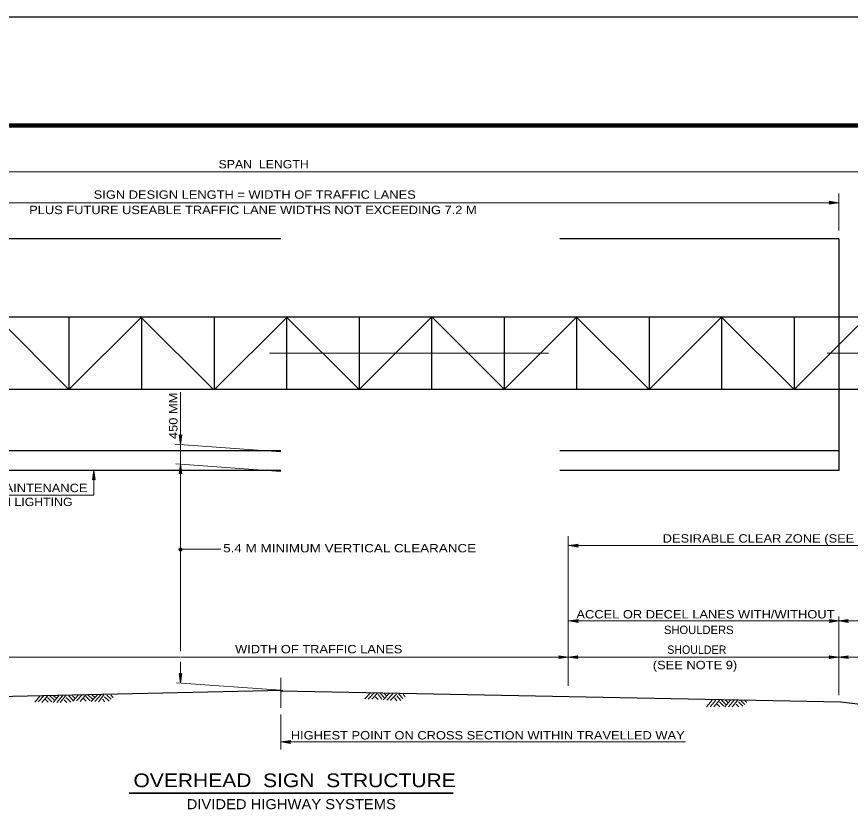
# Model space of a CAD drawing. Extents: x 312601.858 to 312602.699, y 144420.127 to 144420.721.
# Drawn here: x 312602.1123 to 312602.4113, y 144420.4365 to 144420.7208 of the extents above; entities that cross this region are included whole.
import ezdxf
from ezdxf.enums import TextEntityAlignment as Align

# ---------------------------------------------------------------- set-up
doc = ezdxf.new("R2010")
doc.units = 0
doc.header["$LTSCALE"] = 0.0012
doc.linetypes.add('DOT_DASHED', pattern=[7.7, 5, -1.2, 0.3, -1.2])
doc.linetypes.add('LONG_DASHED', pattern=[7.5, 6, -1.5])
for name, color, linetype, lineweight in [('1', 7, 'Continuous', 13), ('2', 7, 'Continuous', 13), ('39', 7, 'Continuous', 13)]:
    doc.layers.add(name, color=color, linetype=linetype, lineweight=lineweight)

msp = doc.modelspace()

# ---------------------------------------------------------------- hatches: boundary and pattern name
at = {"layer": '39'}
for points in [[(312602.404, 144420.6541), (312602.4037, 144420.6546), (312602.4071, 144420.6541), (312602.4037, 144420.6536)], [(312602.404, 144420.6541), (312602.4037, 144420.6546), (312602.4071, 144420.6541), (312602.4037, 144420.6536)], [(312602.1711, 144420.5705), (312602.1716, 144420.5708), (312602.1711, 144420.5674), (312602.1706, 144420.5708)], [(312602.1711, 144420.5705), (312602.1716, 144420.5708), (312602.1711, 144420.5674), (312602.1706, 144420.5708)], [(312602.14, 144420.555), (312602.1395, 144420.5547), (312602.14, 144420.5581), (312602.1405, 144420.5547)], [(312602.1711, 144420.5572), (312602.1706, 144420.5569), (312602.1711, 144420.5603), (312602.1716, 144420.5569)], [(312602.1711, 144420.5572), (312602.1706, 144420.5569), (312602.1711, 144420.5603), (312602.1716, 144420.5569)], [(312602.3134, 144420.5311), (312602.3137, 144420.5306), (312602.3103, 144420.5311), (312602.3137, 144420.5316)], [(312602.3134, 144420.5311), (312602.3137, 144420.5306), (312602.3103, 144420.5311), (312602.3137, 144420.5316)], [(312602.1717, 144420.5297, 1), (312602.1705, 144420.5297, 1)], [(312602.3134, 144420.5041), (312602.3137, 144420.5036), (312602.3103, 144420.5041), (312602.3137, 144420.5046)], [(312602.3134, 144420.5041), (312602.3137, 144420.5036), (312602.3103, 144420.5041), (312602.3137, 144420.5046)], [(312602.4041, 144420.5041), (312602.4038, 144420.5046), (312602.4072, 144420.5041), (312602.4038, 144420.5036)], [(312602.4041, 144420.5041), (312602.4038, 144420.5046), (312602.4072, 144420.5041), (312602.4038, 144420.5036)], [(312602.4102, 144420.5041), (312602.4105, 144420.5036), (312602.4071, 144420.5041), (312602.4105, 144420.5046)], [(312602.307, 144420.4911), (312602.3067, 144420.4916), (312602.3101, 144420.4911), (312602.3067, 144420.4906)], [(312602.3132, 144420.4911), (312602.3135, 144420.4906), (312602.3101, 144420.4911), (312602.3135, 144420.4916)], [(312602.3132, 144420.4911), (312602.3135, 144420.4906), (312602.3101, 144420.4911), (312602.3135, 144420.4916)], [(312602.404, 144420.4911), (312602.4037, 144420.4916), (312602.4071, 144420.4911), (312602.4037, 144420.4906)], [(312602.404, 144420.4911), (312602.4037, 144420.4916), (312602.4071, 144420.4911), (312602.4037, 144420.4906)], [(312602.4102, 144420.4911), (312602.4105, 144420.4906), (312602.4071, 144420.4911), (312602.4105, 144420.4916)], [(312602.4102, 144420.4911), (312602.4105, 144420.4906), (312602.4071, 144420.4911), (312602.4105, 144420.4916)], [(312602.1711, 144420.4849), (312602.1716, 144420.4852), (312602.1711, 144420.4818), (312602.1706, 144420.4852)], [(312602.1711, 144420.4849), (312602.1716, 144420.4852), (312602.1711, 144420.4818), (312602.1706, 144420.4852)], [(312602.2102, 144420.4607), (312602.2105, 144420.4602), (312602.2071, 144420.4607), (312602.2105, 144420.4612)]]:
    msp.add_hatch(color=256, dxfattribs=at).paths.add_polyline_path(points)

# ---------------------------------------------------------------- linework, layer by layer
at = {"layer": '1'}
for p, q in [((312602.1188, 144420.475), (312602.1208, 144420.4773)), ((312602.1201, 144420.4751), (312602.1222, 144420.4774)), ((312602.1214, 144420.4749), (312602.1234, 144420.4773)), ((312602.1242, 144420.4773), (312602.1258, 144420.4758)), ((312602.1254, 144420.4749), (312602.1275, 144420.4772)), ((312602.1256, 144420.4773), (312602.1265, 144420.4765)), ((312602.1267, 144420.4749), (312602.1288, 144420.4773)), ((312602.128, 144420.4748), (312602.1299, 144420.4773)), ((312602.131, 144420.4772), (312602.1325, 144420.4757)), ((312602.1324, 144420.4772), (312602.1332, 144420.4764)), ((312602.1325, 144420.4753), (312602.1345, 144420.4776)), ((312602.1338, 144420.4754), (312602.1359, 144420.4777)), ((312602.1351, 144420.4752), (312602.1371, 144420.4776)), ((312602.1379, 144420.4776), (312602.1395, 144420.4761)), ((312602.1391, 144420.4752), (312602.1412, 144420.4775)), ((312602.1393, 144420.4776), (312602.1402, 144420.4768)), ((312602.1404, 144420.4752), (312602.1425, 144420.4776)), ((312602.1417, 144420.4751), (312602.1436, 144420.4776)), ((312602.1447, 144420.4775), (312602.1462, 144420.476)), ((312602.1461, 144420.4775), (312602.1469, 144420.4767)), ((312602.2372, 144420.4762), (312602.2393, 144420.4784)), ((312602.2384, 144420.4761), (312602.2406, 144420.4784)), ((312602.2397, 144420.476), (312602.2418, 144420.4783)), ((312602.2419, 144420.4777), (312602.2433, 144420.476)), ((312602.2427, 144420.4782), (312602.2441, 144420.4767)), ((312602.2437, 144420.4758), (312602.2459, 144420.4781)), ((312602.2441, 144420.4782), (312602.2448, 144420.4773)), ((312602.2451, 144420.4757), (312602.2472, 144420.478)), ((312602.2463, 144420.4756), (312602.2485, 144420.4779)), ((312602.2486, 144420.4773), (312602.2501, 144420.4756)), ((312602.2494, 144420.4778), (312602.2508, 144420.4763)), ((312602.2509, 144420.4778), (312602.2516, 144420.4769)), ((312602.1226, 144420.476), (312602.1236, 144420.475)), ((312602.1234, 144420.4767), (312602.125, 144420.4751)), ((312602.1294, 144420.4758), (312602.1303, 144420.4748)), ((312602.1301, 144420.4766), (312602.1318, 144420.475)), ((312602.1363, 144420.4763), (312602.1373, 144420.4753)), ((312602.1371, 144420.477), (312602.1387, 144420.4754)), ((312602.1431, 144420.4761), (312602.144, 144420.4751)), ((312602.1438, 144420.4769), (312602.1455, 144420.4753)), ((312602.241, 144420.4769), (312602.242, 144420.4759)), ((312602.2478, 144420.4765), (312602.2487, 144420.4755)), ((312602.3597, 144420.4733), (312602.3617, 144420.4757)), ((312602.361, 144420.4733), (312602.363, 144420.4757)), ((312602.3623, 144420.4733), (312602.3643, 144420.4757)), ((312602.3635, 144420.4743), (312602.3645, 144420.4733)), ((312602.3643, 144420.4751), (312602.3659, 144420.4735)), ((312602.3651, 144420.4757), (312602.3666, 144420.4742)), ((312602.3663, 144420.4733), (312602.3683, 144420.4757)), ((312602.3665, 144420.4757), (312602.3673, 144420.4749)), ((312602.3676, 144420.4733), (312602.3696, 144420.4757)), ((312602.3689, 144420.4733), (312602.3709, 144420.4757)), ((312602.3703, 144420.4743), (312602.3713, 144420.4733)), ((312602.3711, 144420.4751), (312602.3727, 144420.4735)), ((312602.3719, 144420.4757), (312602.3734, 144420.4742)), ((312602.3733, 144420.4757), (312602.3741, 144420.4749))]:
    msp.add_line(p, q, dxfattribs=at)
at = {"layer": '2'}
for p, q in [((312602.14, 144420.5493), (312602.14, 144420.5581)), ((312602.064, 144420.5492), (312602.14, 144420.5492))]:
    msp.add_line(p, q, dxfattribs=at)
at = {"layer": '39', "lineweight": 25}
for p, q in [((312601.8578, 144420.7208), (312602.6988, 144420.7208)), ((312602.4758, 144420.6131), (312601.9817, 144420.6131)), ((312602.1311, 144420.5871), (312602.1051, 144420.6131)), ((312602.1311, 144420.6131), (312602.1311, 144420.5871)), ((312602.1311, 144420.5871), (312602.1571, 144420.6131)), ((312602.1829, 144420.5871), (312602.1569, 144420.6131)), ((312602.1571, 144420.6131), (312602.1571, 144420.5871)), ((312602.1831, 144420.6131), (312602.1831, 144420.5871)), ((312602.1833, 144420.5871), (312602.2093, 144420.6131)), ((312602.2091, 144420.6131), (312602.2091, 144420.5871)), ((312602.2351, 144420.5871), (312602.2091, 144420.6131)), ((312602.2351, 144420.6131), (312602.2351, 144420.5871)), ((312602.2351, 144420.5871), (312602.2611, 144420.6131)), ((312602.2611, 144420.6131), (312602.2611, 144420.5871)), ((312602.2873, 144420.5871), (312602.2613, 144420.6131)), ((312602.2871, 144420.6131), (312602.2871, 144420.5871)), ((312602.2871, 144420.5871), (312602.3131, 144420.6131)), ((312602.3131, 144420.6131), (312602.3131, 144420.5871)), ((312602.3391, 144420.5871), (312602.3131, 144420.6131)), ((312602.3391, 144420.6131), (312602.3391, 144420.5871)), ((312602.3391, 144420.5871), (312602.3651, 144420.6131)), ((312602.3651, 144420.6131), (312602.3651, 144420.5871)), ((312602.3911, 144420.5871), (312602.3651, 144420.6131)), ((312602.3911, 144420.6131), (312602.3911, 144420.5871)), ((312602.3911, 144420.5871), (312602.4171, 144420.6131)), ((312602.4764, 144420.5871), (312601.9961, 144420.5871)), ((312602.0225, 144420.4751), (312602.2078, 144420.4793)), ((312602.2071, 144420.4791), (312602.4079, 144420.4751))]:
    msp.add_line(p, q, dxfattribs=at)
at = {"layer": '39', "lineweight": 158}
msp.add_line((312601.9088, 144420.6818), (312602.6838, 144420.6818), dxfattribs=at)
at = {"layer": '39'}
for p, q in [((312602.4726, 144420.6651), (312601.9456, 144420.6651)), ((312602.4071, 144420.6574), (312602.4071, 144420.6441)), ((312602.4071, 144420.6541), (312602.0231, 144420.6541)), ((312602.1311, 144420.5871), (312602.1571, 144420.6131)), ((312602.1311, 144420.5871), (312602.1571, 144420.6131)), ((312602.1311, 144420.5871), (312602.1571, 144420.6131)), ((312602.2351, 144420.5871), (312602.2091, 144420.6131)), ((312602.2351, 144420.5871), (312602.2091, 144420.6131)), ((312602.2071, 144420.5648), (312602.169, 144420.5675)), ((312602.2071, 144420.5577), (312602.1694, 144420.5604)), ((312602.3101, 144420.5345), (312602.3101, 144420.4808)), ((312602.3103, 144420.5311), (312602.4701, 144420.5311)), ((312602.1711, 144420.5298), (312602.1855, 144420.5298)), ((312602.3103, 144420.5041), (312602.4072, 144420.5041)), ((312602.4071, 144420.5057), (312602.4071, 144420.4775)), ((312602.4071, 144420.5041), (312602.4701, 144420.5041)), ((312602.1711, 144420.4895), (312602.1711, 144420.4818)), ((312602.3253, 144420.4911), (312602.4071, 144420.4911)), ((312602.3253, 144420.4911), (312602.4056, 144420.4911)), ((312602.4071, 144420.4911), (312602.4452, 144420.4911)), ((312602.4096, 144420.4911), (312602.4229, 144420.4911)), ((312602.2071, 144420.4793), (312602.1696, 144420.4819)), ((312602.4066, 144420.4751), (312602.4071, 144420.4751)), ((312602.2071, 144420.4705), (312602.2071, 144420.458)), ((312602.2071, 144420.4607), (312602.3521, 144420.4607))]:
    msp.add_line(p, q, dxfattribs=at)
at = {"layer": '39', "linetype": 'LONG_DASHED', "lineweight": 25}
for p, q in [((312602.4071, 144420.6411), (312602.0231, 144420.6411)), ((312602.4071, 144420.6411), (312602.4071, 144420.5581)), ((312602.4071, 144420.5651), (312602.0231, 144420.5651)), ((312602.4071, 144420.5581), (312602.0231, 144420.5581))]:
    msp.add_line(p, q, dxfattribs=at)
at = {"layer": '39', "linetype": 'DOT_DASHED'}
for p, q in [((312602.003, 144420.6001), (312602.4887, 144420.6001)), ((312602.2071, 144420.4837), (312602.2071, 144420.4729))]:
    msp.add_line(p, q, dxfattribs=at)
at = {"layer": '39', "lineweight": 35}
msp.add_line((312602.1527, 144420.4423), (312602.2688, 144420.4423), dxfattribs=at)
at = {"layer": '39'}
for points in [[(312602.404, 144420.6541), (312602.4037, 144420.6546), (312602.4071, 144420.6541), (312602.4037, 144420.6536)], [(312602.404, 144420.6541), (312602.4037, 144420.6546), (312602.4071, 144420.6541), (312602.4037, 144420.6536)], [(312602.1711, 144420.5705), (312602.1716, 144420.5708), (312602.1711, 144420.5674), (312602.1706, 144420.5708)], [(312602.1711, 144420.5705), (312602.1716, 144420.5708), (312602.1711, 144420.5674), (312602.1706, 144420.5708)], [(312602.14, 144420.555), (312602.1395, 144420.5547), (312602.14, 144420.5581), (312602.1405, 144420.5547)], [(312602.1711, 144420.5572), (312602.1706, 144420.5569), (312602.1711, 144420.5603), (312602.1716, 144420.5569)], [(312602.1711, 144420.5572), (312602.1706, 144420.5569), (312602.1711, 144420.5603), (312602.1716, 144420.5569)], [(312602.3134, 144420.5311), (312602.3137, 144420.5306), (312602.3103, 144420.5311), (312602.3137, 144420.5316)], [(312602.3134, 144420.5311), (312602.3137, 144420.5306), (312602.3103, 144420.5311), (312602.3137, 144420.5316)], [(312602.3134, 144420.5041), (312602.3137, 144420.5036), (312602.3103, 144420.5041), (312602.3137, 144420.5046)], [(312602.3134, 144420.5041), (312602.3137, 144420.5036), (312602.3103, 144420.5041), (312602.3137, 144420.5046)], [(312602.4041, 144420.5041), (312602.4038, 144420.5046), (312602.4072, 144420.5041), (312602.4038, 144420.5036)], [(312602.4041, 144420.5041), (312602.4038, 144420.5046), (312602.4072, 144420.5041), (312602.4038, 144420.5036)], [(312602.4102, 144420.5041), (312602.4105, 144420.5036), (312602.4071, 144420.5041), (312602.4105, 144420.5046)], [(312602.307, 144420.4911), (312602.3067, 144420.4916), (312602.3101, 144420.4911), (312602.3067, 144420.4906)], [(312602.3132, 144420.4911), (312602.3135, 144420.4906), (312602.3101, 144420.4911), (312602.3135, 144420.4916)], [(312602.3132, 144420.4911), (312602.3135, 144420.4906), (312602.3101, 144420.4911), (312602.3135, 144420.4916)], [(312602.404, 144420.4911), (312602.4037, 144420.4916), (312602.4071, 144420.4911), (312602.4037, 144420.4906)], [(312602.404, 144420.4911), (312602.4037, 144420.4916), (312602.4071, 144420.4911), (312602.4037, 144420.4906)], [(312602.4102, 144420.4911), (312602.4105, 144420.4906), (312602.4071, 144420.4911), (312602.4105, 144420.4916)], [(312602.4102, 144420.4911), (312602.4105, 144420.4906), (312602.4071, 144420.4911), (312602.4105, 144420.4916)], [(312602.1711, 144420.4849), (312602.1716, 144420.4852), (312602.1711, 144420.4818), (312602.1706, 144420.4852)], [(312602.1711, 144420.4849), (312602.1716, 144420.4852), (312602.1711, 144420.4818), (312602.1706, 144420.4852)], [(312602.2102, 144420.4607), (312602.2105, 144420.4602), (312602.2071, 144420.4607), (312602.2105, 144420.4612)]]:
    msp.add_lwpolyline(points, close=True, dxfattribs=at)
for points in [[(312602.1711, 144420.5862), (312602.1711, 144420.5674), (312602.1711, 144420.5603), (312602.1711, 144420.4933)], [(312602.0716, 144420.4911), (312602.1041, 144420.4911), (312602.1711, 144420.4911)], [(312602.1713, 144420.4911), (312602.3101, 144420.4911), (312602.327, 144420.4911)]]:
    msp.add_lwpolyline(points, dxfattribs=at)
at = {"layer": '39', "lineweight": 25}
msp.add_lwpolyline([(312602.4079, 144420.4751), (312602.4726, 144420.4673), (312602.5013, 144420.4651)], dxfattribs=at)
at = {"layer": '39'}
for centre, radius in [((312602.1711, 144420.5297), 0.0006), ((312602.1711, 144420.5298), 0.0002)]:
    msp.add_circle(centre, radius, dxfattribs=at)

# ---------------------------------------------------------------- texts
at = {"layer": '2', "width": 1.15}
msp.add_text('450 MM', height=0.003, rotation=90, dxfattribs=at).set_placement((312602.17, 144420.57765), align=Align.CENTER)
at = {"layer": '2'}
for s, width, p in [('LOWER LIMIT OF MAINTENANCE', 1.15, (312602.0652, 144420.5503)), ('WALKWAY AND SIGN LIGHTING', 1.1, (312602.0652, 144420.5453))]:
    msp.add_text(s, height=0.003, dxfattribs=dict(at, width=width)).set_placement(p)
at = {"layer": '39'}
for s, height, width, p in [('SPAN  LENGTH', 0.003, 1.1, (312602.2009, 144420.6664)), ('SIGN DESIGN LENGTH = WIDTH OF TRAFFIC LANES', 0.003, 1.15, (312602.1977, 144420.6555)), ('PLUS FUTURE USEABLE TRAFFIC LANE WIDTHS NOT EXCEEDING 7.2 M', 0.003, 1.15, (312602.19705, 144420.65)), ('DESIRABLE CLEAR ZONE (SEE NOTE 8) ', 0.003, 1.15, (312602.3887, 144420.5322)), ('5.4 M MINIMUM VERTICAL CLEARANCE ', 0.003, 1.2, (312602.2324, 144420.5287)), ('ACCEL OR DECEL LANES WITH/WITHOUT ', 0.003, 1.15, (312602.35995, 144420.505)), ('WIDTH OF TRAFFIC LANES', 0.003, 1.15, (312602.22065, 144420.4925)), ('SHOULDER', 0.003, 0.95, (312602.3562, 144420.4923)), ('(SEE NOTE 9) ', 0.003, 1.15, (312602.3562, 144420.4868)), ('HIGHEST POINT ON CROSS SECTION WITHIN TRAVELLED WAY', 0.003, 1.15, (312602.28125, 144420.4616)), ('OVERHEAD  SIGN  STRUCTURE', 0.0049, 1.15, (312602.212, 144420.4445)), ('DIVIDED HIGHWAY SYSTEMS', 0.0036, 1.1, (312602.2108, 144420.4366))]:
    msp.add_text(s, height=height, dxfattribs=dict(at, width=width)).set_placement(p, align=Align.CENTER)
msp.add_text('SHOULDERS', height=0.003, dxfattribs=at).set_placement((312602.3569, 144420.4994), align=Align.CENTER)

doc.saveas('drawing.dxf')
